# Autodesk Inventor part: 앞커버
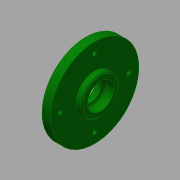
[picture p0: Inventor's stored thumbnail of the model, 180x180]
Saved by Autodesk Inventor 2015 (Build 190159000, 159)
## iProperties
Created: 2015-09
Part Number: 앞커버
Material: 알루미늄 6061
Document SubType Name: Modeling
Designer: mduedu
Density: 2.71 g/cm^3
Mass: 58.9874 g
Surface Area: 98.7754 cm^2
Volume: 21.7666 cm^3
Appearance: 진녹색
Author: mduedu
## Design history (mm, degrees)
sketch "스케치1"
  geometry: L1 (-6.5, 63)-(-11.5, 63); L2 (-11.5, 63)-(-11.5, 84.5); L3 (-11.5, 84.5)-(-19.5, 84.5); L4 (-19.5, 84.5)-(-19.5, 70.5); L5 (-24.5, 70.5)-(-24.5, 54.5); L6 (-24.5, 54.5)-(-6.5, 54.5); L7 (-6.5, 54.5)-(-6.5, 63); L8 (-79.5, 39.5)-(-79.5, 54.5) reference; L9 (48.5, 54.5)-(48.5, 39.5) reference; L10 (-79.5, 47)-(48.5, 47); L11 (-19.5, 70.5)-(-24.5, 70.5); 3 further points
  constraints: 18 end point, 6 parallel, 4 midpoint, 1 horizontal, 1 perpendicular, 1 vertical alignment
  dimensions: "d0" = 18 distance between parallel lines of L7 L5; "d3" = 32 diameter of L1 L10; "d5" = 5 distance of L1.start L1.end; "d6" = 75 diameter of L3 L10; "d7" = 8 distance of L2.end L3.end; "d8" = 47 diameter of L4.end L10; "d61" = 15 diameter of L6 L10
revolve "회전1" sketch "스케치1" stored, may be unused: angle "d4" = 90 deg
sketch "스케치2"
  geometry: C1 r 37.5 at (0, 0) reference; 2 further points
  constraints: 1 coincident
hole "구멍1" sketch "스케치2" at (0, 0) diameter "d11" = 22; stored, may be unused: countersink angle "d15" = 90 deg, drill point angle "d17" = 0 deg; dims "d12" = 6, "d13" = 4, "d14" = 2, "d16" = 8
fillet "모깎기1" dims "d18" = 3
fillet "모깎기2" dims "d19" = 1
sketch "스케치3"
  geometry: C1 r 37.5 at (0, 0) reference; 2 further points
  constraints: 1 coincident
hole "구멍2" sketch "스케치3" at (0, 0) diameter "d20" = 30; stored, may be unused: countersink angle "d24" = 90 deg, drill point angle "d26" = 0 deg; dims "d21" = 6, "d22" = 4, "d23" = 2, "d25" = 7.5
fillet "모깎기3" dims "d27" = 0.3
chamfer "모따기1" distance "d28" = 1; stored, may be unused: second distance "d29" = 2, angle "d30" = 30 deg
sketch "스케치7" dims "d56" = 58
  geometry: C1 r 37.5 at (0, 0) reference; 5 further points
  constraints: 2 vertical alignment, 1 coincident, 7 other
  dimensions: "d59" = 360 deg dimension on C1.centre point (0, 29) (derived)
hole "구멍4" sketch "스케치7" at (0, 29), (-29, 0), (0, -29), (29, 0) diameter "d48" = 3.4; stored, may be unused: countersink angle "d52" = 90 deg, drill point angle "d54" = 0 deg; dims "d49" = 6, "d50" = 6.5, "d51" = 3.4, "d53" = 8
hole "구멍5" diameter "d64" = 17; stored, may be unused: countersink angle "d68" = 90 deg, drill point angle "d70" = 118 deg; dims "d62" = 10, "d63" = 10, "d65" = 6, "d66" = 4, "d67" = 2, "d69" = 8
chamfer "모따기2" distance "d71" = 1; stored, may be unused: second distance "d72" = 2, angle "d73" = 45 deg
node "솔리드1"
node "참조1"
node "참조2"
